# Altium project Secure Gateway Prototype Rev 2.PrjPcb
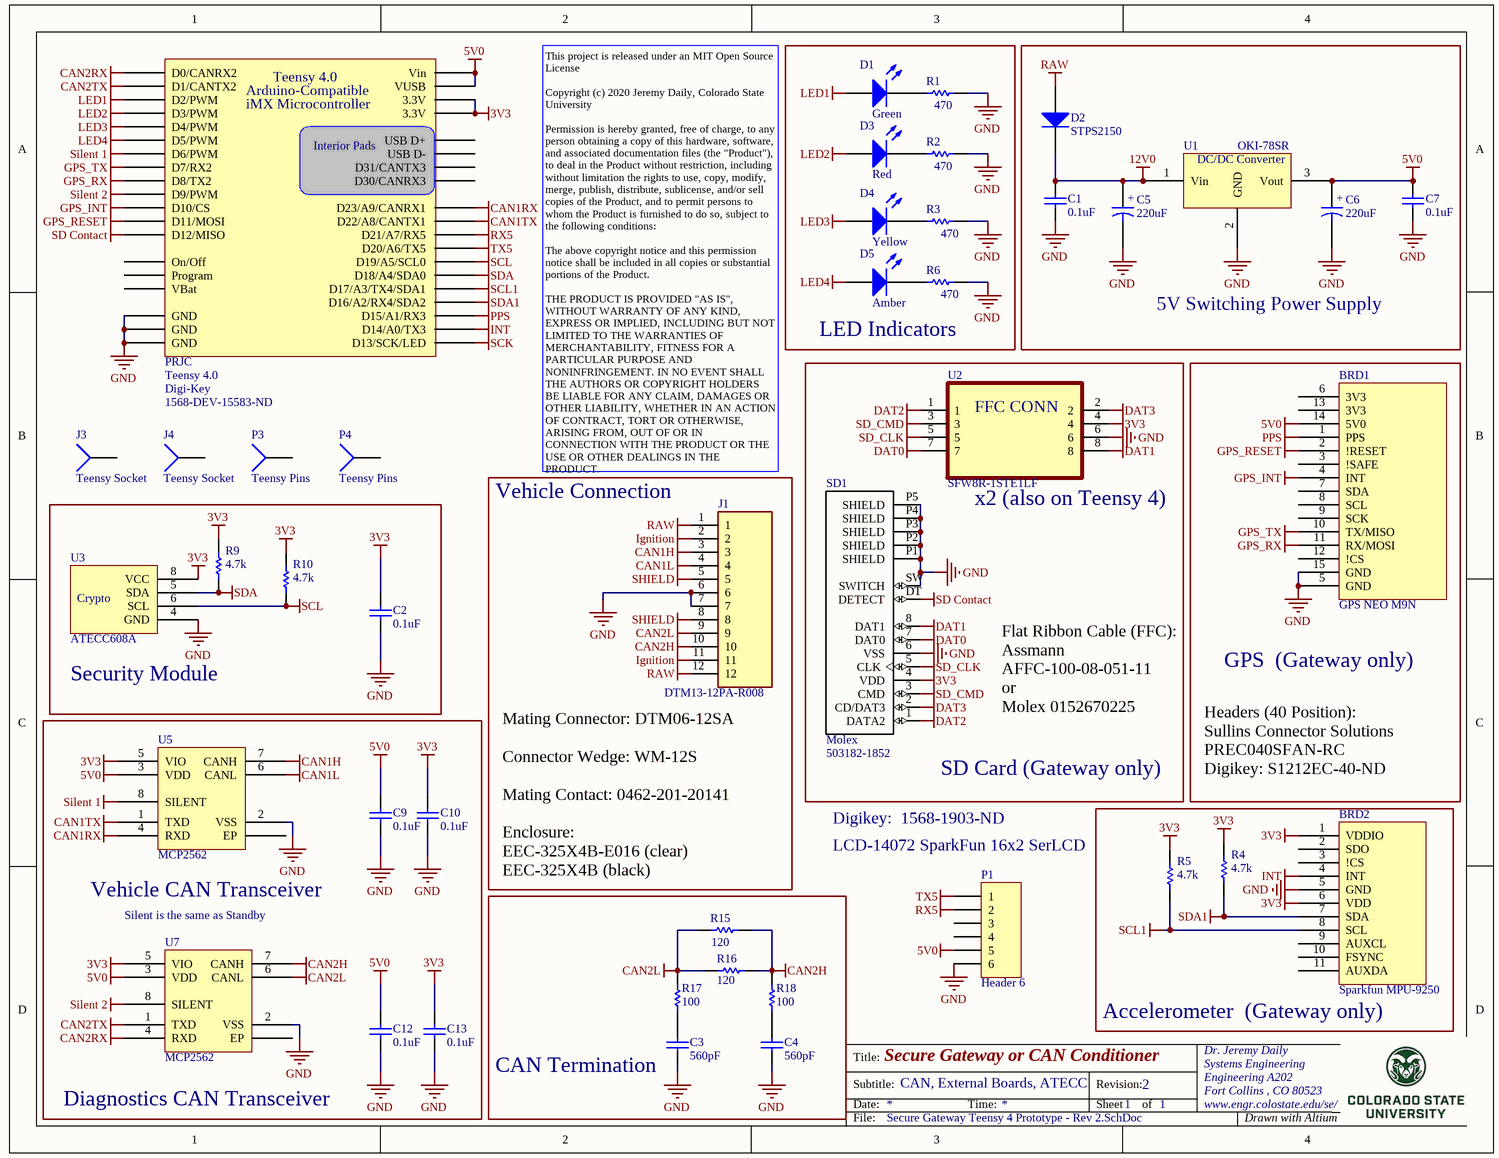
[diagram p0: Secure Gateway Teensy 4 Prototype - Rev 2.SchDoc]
1 sheet, 43 parts. Net scope: global (net labels, ports and power ports of the same name join across sheets).
Board file: Gateway and CAN Conditioner PCB Rev 2.PcbDoc

## Sheet Secure Gateway Teensy 4 Prototype - Rev 2.SchDoc: Secure Gateway or CAN Conditioner
size Letter; Organization: Dr. Jeremy Daily; Address1: Systems Engineering; Address2: Engineering A202; Address3: Fort Collins , CO 80523; Address4: www.engr.colostate.edu/se/; DocumentNumber: CAN, External Boards, ATECC; Revision: 2; SheetNumber: 1; SheetTotal: 1

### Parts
BRD1  GPS NEO M9N  [GPS NEO M9N]
BRD2  Sparkfun MPU-9250  [MPU9250 Breakout]
C1  0.1uF  [CAPR5-4X5]
C2  0.1uF  [CAPR5-4X5]
C3  560pF  [CAPR5-4X5]
C4  560pF  [CAPR5-4X5]
C5  220uF  [Elec. Cap 5 x 10mm]
C6  220uF  [Elec. Cap 5 x 10mm]
C7  0.1uF  [CAPR5-4X5]
C9  0.1uF  [CAPR5-4X5]
C10  0.1uF  [CAPR5-4X5]
C12  0.1uF  [CAPR5-4X5]
C13  0.1uF  [CAPR5-4X5]
D1  Green  [5mm Rad LED]
D2  STPS2150  [DO-204AL]
D3  Red  [5mm Rad LED]
D4  Yellow  [5mm Rad LED]
D5  Amber  [5mm Rad LED]
J1  DTM13-12PA-R008  [TE_DTM13-12PA-R008]
J3  Teensy Socket
J4  Teensy Socket
P1  Header 6  [HDR1X6]
P3  Teensy Pins
P4  Teensy Pins
R1  470  [AXIAL-0.4]
R2  470  [AXIAL-0.4]
R3  470  [AXIAL-0.4]
R4  4.7k  [AXIAL-0.4]
R5  4.7k  [AXIAL-0.4]
R6  470  [AXIAL-0.4]
R9  4.7k  [AXIAL-0.4]
R10  4.7k  [AXIAL-0.4]
R15  120  [AXIAL-0.4]
R16  120  [AXIAL-0.4]
R17  100  [AXIAL-0.4]
R18  100  [AXIAL-0.4]
SD1  503182-1852  Manufacturer: Molex  [MOLEX_503182-1852]
Teensy_1  Manufacturer: PRJC  Supplier 1: Digi-Key  Supplier Part Number 1: 1568-DEV-15583-ND  [Teensy 4.0]  (hidden comment: Teensy 4.0)
U1  OKI-78SR  [OKI-78SR]
U2  SFW8R-1STE1LF  [FCI_SFW8R-1STE1LF]
U3  ATECC608A  [SOIC-8]
U5  MCP2562  [DIP-8]
U7  MCP2562  [DIP-8]

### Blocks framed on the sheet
LED Indicators: D1 D3-D5 R1-R3 R6
5V Switching Power Supply: C1 C5-C7 D2 U1
GPS  (Gateway only): BRD1
Security Module: C2 R9 R10 U3
Vehicle Connection: J1
Accelerometer  (Gateway only): BRD2 R4 R5
CAN Termination: C3 C4 R15-R18

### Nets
3V3: BRD2.1(VDDIO) BRD2.6(VDD) C2.2 C10.2 C13.2 R4.1 R5.1 R9.1 R10.1 SD1.4(VDD) Teensy_1.3V3a(3.3V) Teensy_1.3V3b(3.3V) U2.4 U3.8(VCC) U5.5(VIO) U7.5(VIO)
5V0: BRD1.14(5V0) C6.1 C7.2 C9.2 C12.2 P1.5 Teensy_1.Vin Teensy_1.VUSB U1.3(Vout) U5.3(VDD) U7.3(VDD)
12V0: C1.2 C5.1 D2.2(K) U1.1(Vin)
CAN1H: J1.3 U5.7(CANH)
CAN1L: J1.4 U5.6(CANL)
CAN1RX: Teensy_1.23(D23/A9/CANRX1) U5.4(RXD)
CAN1TX: Teensy_1.22(D22/A8/CANTX1) U5.1(TXD)
CAN2H: J1.10 R15.2 R16.2 R18.2 U7.7(CANH)
CAN2L: J1.9 R15.1 R16.1 R17.2 U7.6(CANL)
CAN2RX: Teensy_1.0(D0/CANRX2) U7.4(RXD)
CAN2TX: Teensy_1.1(D1/CANTX2) U7.1(TXD)
DAT0: SD1.7(DAT0) U2.7
DAT1: SD1.8(DAT1) U2.8
DAT2: SD1.1(DATA2) U2.1
DAT3: SD1.2(CD/DAT3) U2.2
GND: BRD1.5(GND) BRD1.15(GND) BRD2.5(GND) C1.1 C2.1 C3.2 C4.2 C5.2(-) C6.2(-) C7.1 C9.1 C10.1 C12.1 C13.1 J1.6 J1.7 P1.6 R1.2 R2.2 R3.2 R6.2 SD1.6(VSS) SD1.P1(SHIELD) SD1.P2(SHIELD) SD1.P3(SHIELD) SD1.P4(SHIELD) SD1.P5(SHIELD) SD1.SW(SWITCH) Teensy_1.G1(GND) Teensy_1.G2(GND) Teensy_1.G3(GND) U1.2(GND) U2.6 U3.4(GND) U5.2(VSS) U7.2(VSS)
GPS_INT: BRD1.4(INT) Teensy_1.10(D10/CS)
GPS_RESET: BRD1.2(!RESET) Teensy_1.11(D11/MOSI)
GPS_RX: BRD1.11(RX/MOSI) Teensy_1.8(D8/TX2)
GPS_TX: BRD1.10(TX/MISO) Teensy_1.7(D7/RX2)
Ignition: J1.2 J1.11
INT: BRD2.4(INT) Teensy_1.14(D14/A0/TX3)
LED1: D1.1(A) Teensy_1.2(D2/PWM)
LED2: D3.1(A) Teensy_1.3(D3/PWM)
LED3: D4.1(A) Teensy_1.4(D4/PWM)
LED4: D5.1(A) Teensy_1.5(D5/PWM)
PPS: BRD1.1(PPS) Teensy_1.15(D15/A1/RX3)
RAW: D2.1(A) J1.1 J1.12
RX5: P1.2 Teensy_1.21(D21/A7/RX5)
SCK: Teensy_1.13(D13/SCK/LED)
SCL: R10.2 Teensy_1.19(D19/A5/SCL0) U3.6(SCL)
SCL1: BRD2.8(SCL) R5.2 Teensy_1.17(D17/A3/TX4/SDA1)
SD Contact: SD1.DT(DETECT) Teensy_1.12(D12/MISO)
SD_CLK: SD1.5(CLK) U2.5
SD_CMD: SD1.3(CMD) U2.3
SDA: R9.2 Teensy_1.18(D18/A4/SDA0) U3.5(SDA)
SDA1: BRD2.7(SDA) R4.2 Teensy_1.16(D16/A2/RX4/SDA2)
SHIELD: J1.5 J1.8
Silent 1: Teensy_1.6(D6/PWM) U5.8(SILENT)
Silent 2: Teensy_1.9(D9/PWM) U7.8(SILENT)
TX5: P1.1 Teensy_1.20(D20/A6/TX5)
NetC3_1: C3.1 R17.1
NetC4_1: C4.1 R18.1
NetD1_2: D1.2(K) R1.1
NetD3_2: D3.2(K) R2.1
NetD4_2: D4.2(K) R3.1
NetD5_2: D5.2(K) R6.1

Not connected (* = marked no-connect by the designer): BRD1 3(!SAFE) 6(3V3) 7(SDA) 8(SCL) 9(SCK) 12(!CS) 13(3V3); BRD2 2(SDO) 3(!CS) 9(AUXCL) 10(FSYNC) 11(AUXDA); J3 1; J4 1; P1 3 4; P3 1; P4 1; Teensy_1 CRX3(D30/CANRX3) CTX3(D31/CANTX3) D+(USB_D+) D-(USB_D-) On(On/Off) P(Program) VBat; U5 0(EP); U7 0(EP)

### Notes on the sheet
- (near U2) FFC CONN
- This project is released under an MIT Open Source License
  Copyright (c) 2020 Jeremy Daily, Colorado State University
  Permission is hereby granted, free of charge, to any person obtaining a copy of this hardware, software, and associated documentation files (the "Product"), to deal in the Product without restriction, including without limitation the rights to use, copy, modify, merge, publish, distribute, sublicense, and/or sell copies of the Product, and to permit persons to whom the Product is furnished to do so, subject to the following conditions:
  The above copyright notice and this permission notice shall be included in all copies or substantial portions of the Product.
  THE PRODUCT IS PROVIDED "AS IS", WITHOUT WARRANTY OF ANY KIND, EXPRESS OR IMPLIED, INCLUDING BUT NOT LIMITED TO THE WARRANTIES OF MERCHANTABILITY, FITNESS FOR A PARTICULAR PURPOSE AND NONINFRINGEMENT. IN NO EVENT SHALL THE AUTHORS OR COPYRIGHT HOLDERS BE LIABLE FOR ANY CLAIM, DAMAGES OR OTHER LIABILITY, WHETHER IN AN ACTION OF CONTRACT, TORT OR OTHERWISE, ARISING FROM, OUT OF OR IN CONNECTION WITH THE PRODUCT OR THE USE OR OTHER DEALINGS IN THE PRODUCT.
- (near U2) x2 (also on Teensy 4)
- SD Card (Gateway only)
- Digikey:  1568-1903-ND
- Flat Ribbon Cable (FFC):
  Assmann
  AFFC-100-08-051-11
  or
  Molex 0152670225
- Headers (40 Position):
  Sullins Connector Solutions
  PREC040SFAN-RC
  Digikey: S1212EC-40-ND
- Vehicle CAN Transceiver
- Mating Connector: DTM06-12SA
  Connector Wedge: WM-12S
  Mating Contact: 0462-201-20141
  Enclosure:
  EEC-325X4B-E016 (clear)
  EEC-325X4B (black)
- (near P1) LCD-14072 SparkFun 16x2 SerLCD
- (near U7) Silent is the same as Standby
- Diagnostics CAN Transceiver

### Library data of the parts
BRD1 = GPS NEO M9N: Manufacturer: SparkFun Electronics; PartNumber: GPS-15733
BRD2 = MPU-9350 Breakout: Manufacturer: SparkFun Electronics; PartNumber: SEN-13762
C1 C2 C7 C9 C10 C12 C13 = Cap: 0.1µF ±10% 50V Ceramic Capacitor X7R Radial; Manufacturer: TDK Corporation; PartNumber: FA28X7R1H104KNU00; Alternative: Acceptable
C3 C4 = Cap: 560pF ±5% 100V Ceramic Capacitor C0G, NP0 Radial; Manufacturer: TDK Corporation; PartNumber: FA28C0G2A561JNU00; Alternative: Acceptable
C5 C6 = Electrolytic Cap: 220µF 50V Aluminum Electrolytic Capacitors Radial, Can 175 mOhm @ 10kHz 5000 Hrs @ 105°C; Manufacturer: EPCOS (TDK); PartNumber: B41858C6227M000
D1 = LED - SMD: Green 569nm LED Indication - Discrete 2.1V Radial; Manufacturer: Lite-On Inc.
D2 = Diode 1N4003: Diode Schottky 150V 2A Through Hole DO-15; Manufacturer: STMicroelectronics
D3 = LED - SMD: Red 623nm LED Indication - Discrete 2V Radial; Manufacturer: Lite-On Inc.
D4 = LED - SMD: Yellow 588nm LED Indication - Discrete 2.1V Radial; Manufacturer: Lite-On Inc.
D5 = LED - SMD: Amber 588nm LED Indication - Discrete 2.1V Radial; Manufacturer: Lite-On Inc.
J1 = DTM13-12PA-R008: DTM Series, 4.19mm Pitch 12 Way 2 Row Right Angle PCB Header, Solder Termination; Manufacturer: TE Connectivity Deutsch Connectors
J3 J4 = Socket: 14 Position Header Connector  Through Hole; Manufacturer: Sullins Connector Solutions; PartNumber: PPTC141LFBN-RC
P1 = Header 6: Header, 6-Pin; Manufacturer: Sullins Connector Solutions; PartNumber: PREC040SFAN-RC‎
P3 P4 = Socket: Connector Header Through Hole 14 position 0.100" (2.54mm); Manufacturer: Sullins Connector Solutions; PartNumber: PREC014SAAN-RC
R1-R3 R6 = Chip Resistor: 330 Ohms ±1% 0.1W, 1/10W Chip Resistor 0603 (1608 Metric) Automotive AEC-Q200, High Voltage Thick Film; Manufacturer: Stackpole Electronics Inc; PartNumber: CF14JT470R; Alternative: Acceptable
R4 R5 R9 R10 = Chip Resistor: 4.7 kOhms ±5% 0.25W, 1/4W Through Hole Resistor Axial Flame Retardant Coating, Safety Carbon Film; Manufacturer: Stackpole Electronics Inc; PartNumber: CF14JT4K70; Alternative: Acceptable
R15 R16 = Chip Resistor: 120 Ohms ±5% 0.25W, 1/4W Through Hole Resistor Axial Flame Retardant Coating, Safety Carbon Film; Manufacturer: Stackpole Electronics Inc; PartNumber: CF14JT120RCT-ND; Alternative: Acceptable
R17 R18 = Chip Resistor: 100 Ohms ±5% 0.25W, 1/4W Through Hole Resistor Axial Flame Retardant Coating, Safety Carbon Film; Manufacturer: Stackpole Electronics Inc; PartNumber: CF14JT100R; Alternative: Acceptable
SD1 = 503182-1852: MICRO SD NORMAL ULTRALOWPRO8CKTE; PartNumber: 5031821852
Teensy_1 = Teensy_4.0: 32 Bit Arduino-Compatible iMX Microcontroller
U1 = 7805: 5V DC/DC Converter (7805 replacement); Manufacturer: Murata Power Solutions Inc.; PartNumber: OKI-78SR-5/1.5-W36H-C
U2 = SFW8R-1STE1LF: 8 Position FFC, FPC Connector Contacts, Bottom 0.039 _1.00mm_ Surface Mount, Right Angle; Manufacturer: Amphenol ICC
U3 = ATECC508A: Authentication Chip IC Networking and Communications 8-SOIC; Manufacturer: Microchip Technology; PartNumber: ATECC608A-SSHDA-T
U5 U7 = MCP2558FD: Microchip CAN FD Transceiver with Silent Mode; PartNumber: MCP2562-E/P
